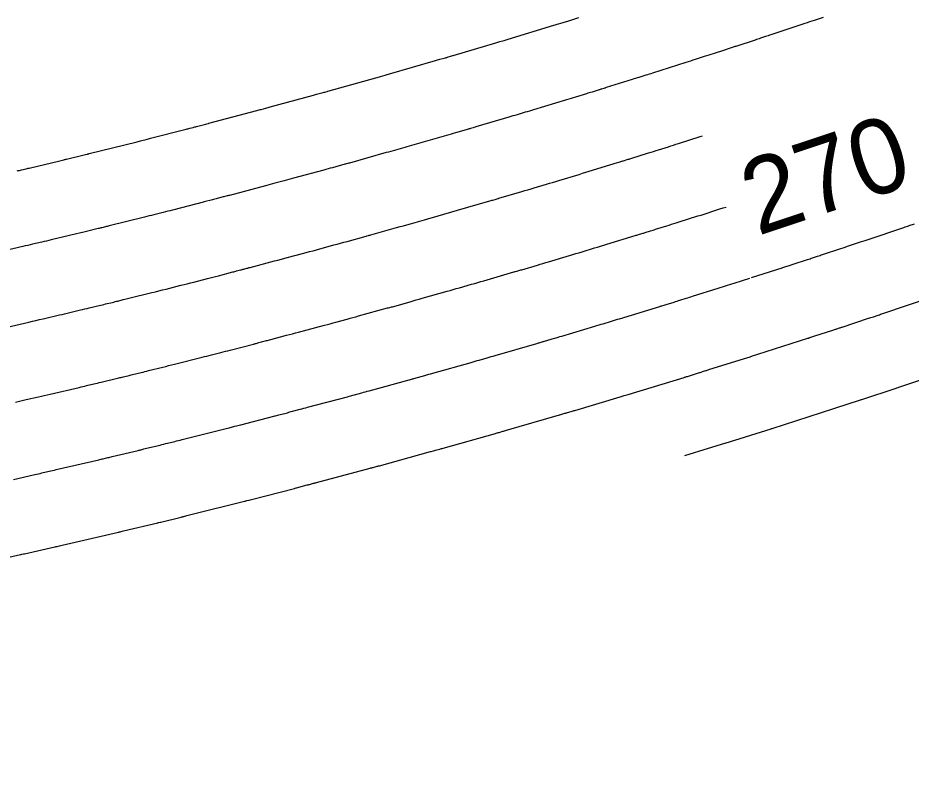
# Model space of a CAD drawing. Extents: x 1710723 to 1713003, y 548603 to 551142.
# Drawn here: x 1711864.8 to 1711936.3, y 549143.7 to 549204.1 of the extents above; entities that cross this region are included whole.
import ezdxf

# ---------------------------------------------------------------- set-up
doc = ezdxf.new("R2010")
doc.units = 0
for name, color, linetype in [('R_Contour Annot', 7, 'Continuous'), ('R_Contours', 7, 'Continuous'), ('R_Horz Alg', 7, 'Continuous')]:
    doc.layers.add(name, color=color, linetype=linetype)

msp = doc.modelspace()

# ---------------------------------------------------------------- linework, layer by layer
at = {"layer": 'R_Contours'}
for points in [[(1711929.262, 549204.147), (1711928.537, 549203.903), (1711928.356, 549203.842), (1711928.175, 549203.781), (1711927.994, 549203.721), (1711927.813, 549203.66), (1711925.076, 549202.746), (1711924.972, 549202.711), (1711924.869, 549202.677), (1711924.765, 549202.642), (1711924.661, 549202.608), (1711924.246, 549202.471), (1711924.142, 549202.437), (1711924.038, 549202.402), (1711923.934, 549202.368), (1711923.83, 549202.334), (1711922.285, 549201.828), (1711922.209, 549201.803), (1711922.132, 549201.777), (1711922.055, 549201.752), (1711921.978, 549201.727), (1711921.671, 549201.627), (1711921.594, 549201.602), (1711921.517, 549201.577), (1711921.44, 549201.552), (1711921.363, 549201.527), (1711920.457, 549201.233), (1711920.28, 549201.176), (1711920.104, 549201.119), (1711919.927, 549201.062), (1711919.75, 549201.005), (1711919.012, 549200.769), (1711918.83, 549200.71), (1711918.649, 549200.652), (1711918.467, 549200.594), (1711918.285, 549200.536), (1711915.597, 549199.68), (1711915.463, 549199.637), (1711915.329, 549199.595), (1711915.195, 549199.553), (1711915.061, 549199.511), (1711914.525, 549199.342), (1711914.391, 549199.3), (1711914.257, 549199.258), (1711914.123, 549199.216), (1711913.989, 549199.175), (1711911.901, 549198.523), (1711911.853, 549198.508), (1711911.805, 549198.494), (1711911.758, 549198.479), (1711911.71, 549198.464), (1711911.519, 549198.405), (1711911.471, 549198.39), (1711911.423, 549198.375), (1711911.376, 549198.36), (1711911.328, 549198.346), (1711910.765, 549198.172), (1711910.655, 549198.139), (1711910.546, 549198.105), (1711910.436, 549198.071), (1711910.326, 549198.038), (1711909.449, 549197.77), (1711909.266, 549197.714), (1711909.084, 549197.659), (1711908.901, 549197.603), (1711908.718, 549197.548), (1711906.082, 549196.748), (1711905.917, 549196.699), (1711905.753, 549196.649), (1711905.588, 549196.6), (1711905.424, 549196.551), (1711904.765, 549196.355), (1711904.601, 549196.306), (1711904.436, 549196.257), (1711904.272, 549196.208), (1711904.107, 549196.159), (1711901.473, 549195.379), (1711901.418, 549195.363), (1711901.307, 549195.331), (1711901.252, 549195.314), (1711901.036, 549195.251), (1711900.993, 549195.239), (1711900.951, 549195.227), (1711900.909, 549195.214), (1711900.867, 549195.202), (1711899.849, 549194.907), (1711899.665, 549194.854), (1711899.482, 549194.801), (1711899.298, 549194.748), (1711899.114, 549194.695), (1711896.509, 549193.944), (1711896.325, 549193.892), (1711896.141, 549193.839), (1711895.956, 549193.787), (1711895.772, 549193.735), (1711895.035, 549193.527), (1711894.851, 549193.475), (1711894.667, 549193.423), (1711894.483, 549193.371), (1711894.298, 549193.32), (1711891.344, 549192.491), (1711891.299, 549192.478), (1711891.209, 549192.453), (1711891.077, 549192.417), (1711891.026, 549192.403), (1711890.974, 549192.388), (1711889.985, 549192.117), (1711889.812, 549192.07), (1711889.638, 549192.022), (1711889.465, 549191.975), (1711889.292, 549191.928), (1711886.864, 549191.266), (1711886.679, 549191.215), (1711886.494, 549191.165), (1711886.309, 549191.115), (1711886.123, 549191.066), (1711885.382, 549190.868), (1711885.196, 549190.819), (1711885.011, 549190.769), (1711884.826, 549190.72), (1711884.64, 549190.671), (1711881.741, 549189.901), (1711881.7, 549189.89), (1711881.658, 549189.879), (1711881.617, 549189.868), (1711881.576, 549189.857), (1711881.369, 549189.803), (1711881.286, 549189.781), (1711881.245, 549189.771), (1711880.764, 549189.645), (1711880.67, 549189.621), (1711880.576, 549189.596), (1711880.482, 549189.572), (1711880.388, 549189.548), (1711879.71, 549189.373), (1711879.566, 549189.335), (1711879.422, 549189.298), (1711879.277, 549189.261), (1711879.133, 549189.224), (1711877.187, 549188.723), (1711877.001, 549188.676), (1711876.814, 549188.628), (1711876.628, 549188.581), (1711876.441, 549188.534), (1711875.694, 549188.347), (1711875.508, 549188.3), (1711875.321, 549188.254), (1711875.134, 549188.207), (1711874.948, 549188.16), (1711872.105, 549187.452), (1711872.033, 549187.434), (1711871.961, 549187.416), (1711871.889, 549187.398), (1711871.817, 549187.381), (1711871.529, 549187.31), (1711871.457, 549187.293), (1711871.385, 549187.275), (1711871.313, 549187.258), (1711871.241, 549187.24), (1711870.315, 549187.015), (1711870.2, 549186.987), (1711870.086, 549186.96), (1711869.971, 549186.932), (1711869.856, 549186.905), (1711869.397, 549186.795), (1711869.282, 549186.767), (1711869.167, 549186.74), (1711869.052, 549186.712), (1711868.937, 549186.685), (1711867.473, 549186.336), (1711867.285, 549186.291), (1711867.098, 549186.247), (1711866.91, 549186.203), (1711866.722, 549186.159), (1711865.971, 549185.985), (1711865.783, 549185.941), (1711865.595, 549185.898), (1711865.407, 549185.855), (1711865.219, 549185.811), (1711862.431, 549185.167)], [(1711864.754, 549191.862), (1711864.842, 549191.882), (1711864.931, 549191.903), (1711865.019, 549191.923), (1711865.108, 549191.944), (1711865.462, 549192.026), (1711865.551, 549192.047), (1711865.639, 549192.067), (1711865.728, 549192.088), (1711865.816, 549192.109), (1711868.052, 549192.642), (1711868.161, 549192.668), (1711868.27, 549192.694), (1711868.487, 549192.746), (1711868.542, 549192.759), (1711868.596, 549192.772), (1711868.651, 549192.786), (1711868.705, 549192.799), (1711870.11, 549193.14), (1711870.213, 549193.165), (1711870.384, 549193.207), (1711870.418, 549193.215), (1711870.452, 549193.224), (1711870.486, 549193.232), (1711870.52, 549193.241), (1711874.363, 549194.199), (1711874.452, 549194.221), (1711874.541, 549194.243), (1711874.631, 549194.266), (1711874.72, 549194.288), (1711875.077, 549194.377), (1711875.166, 549194.4), (1711875.255, 549194.422), (1711875.344, 549194.445), (1711875.433, 549194.468), (1711878.284, 549195.201), (1711878.354, 549195.219), (1711878.423, 549195.237), (1711878.492, 549195.255), (1711878.562, 549195.273), (1711878.839, 549195.344), (1711878.908, 549195.362), (1711878.978, 549195.38), (1711879.047, 549195.398), (1711879.116, 549195.416), (1711879.85, 549195.608), (1711879.93, 549195.628), (1711880.029, 549195.654), (1711880.069, 549195.665), (1711880.089, 549195.67), (1711883.936, 549196.692), (1711884.026, 549196.716), (1711884.116, 549196.74), (1711884.206, 549196.763), (1711884.295, 549196.787), (1711884.655, 549196.883), (1711884.745, 549196.907), (1711884.835, 549196.931), (1711884.924, 549196.956), (1711885.014, 549196.98), (1711888.472, 549197.924), (1711888.557, 549197.947), (1711888.642, 549197.97), (1711888.726, 549197.993), (1711888.811, 549198.016), (1711889.257, 549198.138), (1711889.319, 549198.155), (1711889.382, 549198.173), (1711889.574, 549198.226), (1711889.623, 549198.24), (1711893.473, 549199.32), (1711893.564, 549199.345), (1711893.655, 549199.371), (1711893.746, 549199.396), (1711893.837, 549199.422), (1711894.2, 549199.524), (1711894.291, 549199.55), (1711894.381, 549199.576), (1711894.472, 549199.602), (1711894.563, 549199.628), (1711898.229, 549200.684), (1711898.32, 549200.71), (1711898.411, 549200.736), (1711898.503, 549200.763), (1711898.594, 549200.789), (1711899.04, 549200.918), (1711899.091, 549200.933), (1711899.142, 549200.948), (1711899.193, 549200.963), (1711899.244, 549200.978), (1711899.54, 549201.064), (1711899.622, 549201.088), (1711899.64, 549201.094), (1711903.068, 549202.108), (1711903.151, 549202.133), (1711903.233, 549202.157), (1711903.316, 549202.182), (1711903.398, 549202.206), (1711903.729, 549202.305), (1711903.812, 549202.33), (1711903.894, 549202.354), (1711903.977, 549202.379), (1711904.059, 549202.404), (1711907.711, 549203.511), (1711907.804, 549203.54), (1711907.896, 549203.568), (1711907.989, 549203.596), (1711908.082, 549203.624), (1711908.452, 549203.737), (1711908.545, 549203.766), (1711908.638, 549203.794), (1711908.73, 549203.822), (1711908.823, 549203.851), (1711909.642, 549204.103), (1711909.714, 549204.126)], [(1711863.948, 549179.359), (1711865.685, 549179.76), (1711865.972, 549179.827), (1711866.26, 549179.893), (1711866.547, 549179.96), (1711866.834, 549180.026), (1711868.151, 549180.332), (1711868.354, 549180.379), (1711868.556, 549180.426), (1711868.758, 549180.474), (1711868.96, 549180.522), (1711869.822, 549180.728), (1711869.997, 549180.769), (1711870.173, 549180.811), (1711870.348, 549180.853), (1711870.523, 549180.895), (1711871.321, 549181.086), (1711871.448, 549181.116), (1711871.575, 549181.147), (1711871.702, 549181.178), (1711871.829, 549181.209), (1711872.372, 549181.34), (1711872.482, 549181.367), (1711872.592, 549181.394), (1711872.701, 549181.421), (1711872.811, 549181.447), (1711873.25, 549181.554), (1711873.36, 549181.581), (1711873.47, 549181.608), (1711873.579, 549181.635), (1711873.689, 549181.663), (1711875.532, 549182.122), (1711875.816, 549182.193), (1711876.101, 549182.264), (1711876.385, 549182.335), (1711876.669, 549182.406), (1711877.861, 549182.705), (1711878.117, 549182.769), (1711878.373, 549182.834), (1711878.629, 549182.899), (1711878.885, 549182.965), (1711879.981, 549183.246), (1711880.201, 549183.303), (1711880.42, 549183.359), (1711880.639, 549183.416), (1711880.859, 549183.473), (1711882.026, 549183.774), (1711882.1, 549183.793), (1711882.174, 549183.812), (1711882.248, 549183.832), (1711882.322, 549183.851), (1711882.64, 549183.934), (1711882.702, 549183.95), (1711882.765, 549183.966), (1711882.828, 549183.983), (1711882.891, 549183.999), (1711883.142, 549184.065), (1711883.205, 549184.082), (1711883.268, 549184.098), (1711883.331, 549184.115), (1711883.393, 549184.131), (1711885.344, 549184.65), (1711885.625, 549184.724), (1711885.906, 549184.799), (1711886.187, 549184.874), (1711886.468, 549184.949), (1711887.592, 549185.248), (1711887.873, 549185.323), (1711888.154, 549185.399), (1711888.434, 549185.475), (1711888.715, 549185.551), (1711890.111, 549185.932), (1711890.373, 549186.004), (1711890.635, 549186.075), (1711890.897, 549186.147), (1711891.159, 549186.219), (1711892.691, 549186.639), (1711892.753, 549186.655), (1711892.878, 549186.69), (1711892.929, 549186.704), (1711893.014, 549186.728), (1711893.065, 549186.742), (1711895.123, 549187.319), (1711895.401, 549187.397), (1711895.679, 549187.475), (1711895.956, 549187.554), (1711896.234, 549187.632), (1711897.345, 549187.945), (1711897.622, 549188.024), (1711897.9, 549188.102), (1711898.177, 549188.182), (1711898.455, 549188.261), (1711900, 549188.706), (1711900.276, 549188.786), (1711900.552, 549188.866), (1711900.828, 549188.946), (1711901.104, 549189.025), (1711902.693, 549189.486), (1711902.76, 549189.505), (1711902.827, 549189.525), (1711903.002, 549189.576), (1711903.084, 549189.6), (1711903.223, 549189.641), (1711903.278, 549189.657), (1711903.305, 549189.665), (1711905.146, 549190.21), (1711905.392, 549190.283), (1711905.639, 549190.356), (1711905.886, 549190.429), (1711906.132, 549190.503), (1711907.118, 549190.796), (1711907.365, 549190.87), (1711907.611, 549190.944), (1711907.858, 549191.018), (1711908.104, 549191.092), (1711909.725, 549191.584), (1711909.998, 549191.667), (1711910.271, 549191.75), (1711910.544, 549191.833), (1711910.817, 549191.916), (1711912.278, 549192.362), (1711912.366, 549192.389), (1711912.454, 549192.416), (1711912.542, 549192.443), (1711912.629, 549192.47), (1711913.014, 549192.588), (1711913.085, 549192.61), (1711913.157, 549192.632), (1711913.228, 549192.654), (1711913.299, 549192.676), (1711913.584, 549192.765), (1711913.655, 549192.787), (1711913.726, 549192.809), (1711913.798, 549192.831), (1711913.869, 549192.853), (1711915.293, 549193.297), (1711915.492, 549193.36), (1711915.692, 549193.422), (1711915.891, 549193.484), (1711916.09, 549193.547), (1711916.888, 549193.797), (1711917.087, 549193.86), (1711917.287, 549193.923), (1711917.486, 549193.986), (1711917.685, 549194.049), (1711919.414, 549194.6), (1711919.598, 549194.659)], [(1711864.616, 549173.358), (1711864.828, 549173.406), (1711865.041, 549173.454), (1711865.253, 549173.502), (1711865.465, 549173.551), (1711866.453, 549173.779), (1711866.689, 549173.834), (1711866.924, 549173.888), (1711867.159, 549173.943), (1711867.395, 549173.997), (1711869.723, 549174.537), (1711869.869, 549174.571), (1711870.015, 549174.606), (1711870.16, 549174.64), (1711870.306, 549174.674), (1711870.888, 549174.813), (1711871.033, 549174.848), (1711871.178, 549174.883), (1711871.324, 549174.917), (1711871.469, 549174.952), (1711872.881, 549175.29), (1711872.973, 549175.312), (1711873.064, 549175.334), (1711873.156, 549175.356), (1711873.248, 549175.379), (1711873.615, 549175.468), (1711873.706, 549175.49), (1711873.798, 549175.512), (1711873.89, 549175.535), (1711873.982, 549175.557), (1711874.684, 549175.728), (1711874.831, 549175.764), (1711874.979, 549175.801), (1711875.126, 549175.837), (1711875.273, 549175.874), (1711876.405, 549176.156), (1711876.642, 549176.215), (1711876.88, 549176.274), (1711877.118, 549176.334), (1711877.355, 549176.393), (1711879.561, 549176.945), (1711879.747, 549176.992), (1711879.933, 549177.039), (1711880.118, 549177.086), (1711880.304, 549177.134), (1711881.047, 549177.325), (1711881.233, 549177.373), (1711881.418, 549177.421), (1711881.604, 549177.469), (1711881.79, 549177.516), (1711883.665, 549178.001), (1711883.719, 549178.014), (1711883.772, 549178.028), (1711883.826, 549178.042), (1711883.88, 549178.056), (1711884.095, 549178.113), (1711884.203, 549178.141), (1711884.311, 549178.169), (1711884.709, 549178.273), (1711884.793, 549178.295), (1711884.877, 549178.318), (1711884.961, 549178.34), (1711885.046, 549178.362), (1711886.321, 549178.701), (1711886.561, 549178.765), (1711886.802, 549178.829), (1711887.042, 549178.893), (1711887.283, 549178.957), (1711889.358, 549179.51), (1711889.586, 549179.571), (1711889.813, 549179.632), (1711890.041, 549179.694), (1711890.268, 549179.756), (1711891.177, 549180.004), (1711891.405, 549180.066), (1711891.632, 549180.128), (1711891.859, 549180.19), (1711892.086, 549180.252), (1711894.409, 549180.889), (1711894.469, 549180.905), (1711894.574, 549180.934), (1711894.718, 549180.974), (1711894.763, 549180.987), (1711894.786, 549180.993), (1711896.203, 549181.391), (1711896.447, 549181.459), (1711896.691, 549181.528), (1711896.934, 549181.596), (1711897.178, 549181.665), (1711899.168, 549182.226), (1711899.414, 549182.296), (1711899.659, 549182.365), (1711899.905, 549182.436), (1711900.15, 549182.506), (1711901.131, 549182.789), (1711901.377, 549182.859), (1711901.622, 549182.93), (1711901.867, 549183.001), (1711902.113, 549183.072), (1711904.519, 549183.769), (1711904.569, 549183.784), (1711904.619, 549183.798), (1711904.744, 549183.835), (1711904.819, 549183.857), (1711904.991, 549183.907), (1711905.064, 549183.929), (1711905.138, 549183.951), (1711906.398, 549184.324), (1711906.62, 549184.389), (1711906.842, 549184.455), (1711907.064, 549184.521), (1711907.286, 549184.587), (1711908.972, 549185.089), (1711909.221, 549185.164), (1711909.47, 549185.238), (1711909.719, 549185.313), (1711909.967, 549185.388), (1711910.961, 549185.69), (1711911.21, 549185.765), (1711911.458, 549185.841), (1711911.707, 549185.916), (1711911.955, 549185.992), (1711914.23, 549186.686), (1711914.296, 549186.706), (1711914.362, 549186.726), (1711914.428, 549186.747), (1711914.494, 549186.767), (1711914.758, 549186.848), (1711914.824, 549186.869), (1711914.89, 549186.889), (1711914.956, 549186.91), (1711915.022, 549186.93), (1711915.458, 549187.065), (1711915.553, 549187.095), (1711915.647, 549187.124), (1711915.742, 549187.153), (1711915.837, 549187.183), (1711916.757, 549187.47), (1711916.941, 549187.528), (1711917.126, 549187.585), (1711917.311, 549187.643), (1711917.496, 549187.701), (1711918.74, 549188.092), (1711918.992, 549188.171), (1711919.244, 549188.251), (1711919.496, 549188.33), (1711919.747, 549188.41), (1711920.754, 549188.731), (1711921.006, 549188.811), (1711921.258, 549188.892), (1711921.494, 549188.967)], [(1711923.539, 549183.324), (1711925.976, 549184.106), (1711926.049, 549184.13), (1711926.123, 549184.153), (1711926.197, 549184.177), (1711926.271, 549184.201), (1711926.566, 549184.297), (1711926.64, 549184.321), (1711926.713, 549184.345), (1711926.787, 549184.369), (1711926.861, 549184.393), (1711928.013, 549184.769), (1711928.114, 549184.801), (1711928.214, 549184.834), (1711928.314, 549184.867), (1711928.414, 549184.9), (1711928.816, 549185.031), (1711928.916, 549185.064), (1711929.016, 549185.097), (1711929.116, 549185.13), (1711929.217, 549185.163), (1711930.683, 549185.648), (1711930.859, 549185.706), (1711931.035, 549185.764), (1711931.211, 549185.823), (1711931.387, 549185.881), (1711932.09, 549186.116), (1711932.265, 549186.175), (1711932.441, 549186.234), (1711932.617, 549186.293), (1711932.793, 549186.352), (1711935.727, 549187.339), (1711935.832, 549187.375), (1711935.937, 549187.41), (1711936.042, 549187.446), (1711936.147, 549187.482), (1711936.568, 549187.625)], [(1711864.466, 549167.174), (1711866.164, 549167.556), (1711866.306, 549167.588), (1711866.449, 549167.621), (1711866.591, 549167.653), (1711866.734, 549167.686), (1711867.304, 549167.818), (1711867.446, 549167.85), (1711867.588, 549167.883), (1711867.731, 549167.916), (1711867.873, 549167.949), (1711871.295, 549168.743), (1711871.384, 549168.764), (1711871.473, 549168.785), (1711871.562, 549168.806), (1711871.651, 549168.827), (1711872.006, 549168.912), (1711872.095, 549168.933), (1711872.184, 549168.954), (1711872.273, 549168.975), (1711872.362, 549168.997), (1711874.441, 549169.494), (1711874.498, 549169.508), (1711874.554, 549169.521), (1711874.61, 549169.535), (1711874.667, 549169.548), (1711874.892, 549169.603), (1711875.005, 549169.631), (1711875.117, 549169.658), (1711876.194, 549169.921), (1711876.341, 549169.957), (1711876.487, 549169.993), (1711876.634, 549170.029), (1711876.781, 549170.065), (1711877.367, 549170.212), (1711877.513, 549170.248), (1711877.66, 549170.285), (1711877.806, 549170.321), (1711877.953, 549170.358), (1711881.26, 549171.186), (1711881.376, 549171.215), (1711881.492, 549171.244), (1711881.608, 549171.274), (1711881.723, 549171.303), (1711882.186, 549171.422), (1711882.301, 549171.452), (1711882.417, 549171.482), (1711882.532, 549171.512), (1711882.648, 549171.542), (1711885.303, 549172.227), (1711885.371, 549172.245), (1711885.438, 549172.262), (1711885.607, 549172.306), (1711885.708, 549172.333), (1711886.275, 549172.481), (1711886.381, 549172.509), (1711886.487, 549172.537), (1711886.592, 549172.565), (1711886.698, 549172.593), (1711887.394, 549172.778), (1711887.546, 549172.818), (1711887.697, 549172.858), (1711887.848, 549172.898), (1711888, 549172.939), (1711891.183, 549173.788), (1711891.328, 549173.827), (1711891.473, 549173.865), (1711891.617, 549173.905), (1711891.762, 549173.944), (1711892.34, 549174.101), (1711892.484, 549174.141), (1711892.629, 549174.18), (1711892.773, 549174.22), (1711892.917, 549174.259), (1711896.126, 549175.139), (1711896.164, 549175.149), (1711896.241, 549175.171), (1711896.393, 549175.213), (1711896.45, 549175.229), (1711896.507, 549175.245), (1711897.389, 549175.492), (1711897.546, 549175.536), (1711897.702, 549175.58), (1711897.859, 549175.624), (1711898.015, 549175.668), (1711901.1, 549176.538), (1711901.259, 549176.583), (1711901.419, 549176.628), (1711901.578, 549176.674), (1711901.737, 549176.72), (1711902.374, 549176.903), (1711902.533, 549176.949), (1711902.692, 549176.995), (1711902.852, 549177.041), (1711903.011, 549177.087), (1711906.346, 549178.053), (1711906.395, 549178.067), (1711906.493, 549178.096), (1711906.542, 549178.11), (1711906.786, 549178.182), (1711906.832, 549178.195), (1711906.878, 549178.209), (1711906.924, 549178.223), (1711906.97, 549178.236), (1711907.753, 549178.468), (1711907.899, 549178.511), (1711908.045, 549178.555), (1711908.191, 549178.598), (1711908.337, 549178.641), (1711910.999, 549179.434), (1711911.164, 549179.483), (1711911.329, 549179.533), (1711911.493, 549179.582), (1711911.658, 549179.632), (1711912.317, 549179.832), (1711912.481, 549179.882), (1711912.646, 549179.932), (1711912.81, 549179.982), (1711912.975, 549180.032), (1711916.181, 549181.01), (1711916.226, 549181.024), (1711916.27, 549181.037), (1711916.314, 549181.051), (1711916.358, 549181.064), (1711916.535, 549181.119), (1711916.623, 549181.146), (1711916.712, 549181.174), (1711917.332, 549181.366), (1711917.45, 549181.403), (1711917.568, 549181.439), (1711917.687, 549181.476), (1711917.805, 549181.513), (1711918.313, 549181.671), (1711918.437, 549181.71), (1711918.561, 549181.749), (1711918.685, 549181.788), (1711918.809, 549181.826), (1711920.861, 549182.471), (1711921.031, 549182.524), (1711921.201, 549182.578), (1711921.372, 549182.632), (1711921.542, 549182.686), (1711922.222, 549182.903), (1711922.392, 549182.957), (1711922.563, 549183.011), (1711922.733, 549183.066), (1711922.903, 549183.12), (1711923.39, 549183.277)], [(1711862.984, 549160.701), (1711865.019, 549161.149), (1711865.071, 549161.161), (1711865.124, 549161.173), (1711865.255, 549161.202), (1711865.334, 549161.22), (1711867.757, 549161.765), (1711867.807, 549161.776), (1711867.857, 549161.787), (1711867.906, 549161.798), (1711867.956, 549161.81), (1711868.154, 549161.856), (1711868.253, 549161.879), (1711868.352, 549161.902), (1711872.867, 549162.949), (1711872.899, 549162.956), (1711872.931, 549162.964), (1711872.964, 549162.971), (1711872.996, 549162.979), (1711873.158, 549163.018), (1711873.255, 549163.041), (1711876.001, 549163.698), (1711876.043, 549163.708), (1711876.085, 549163.718), (1711876.211, 549163.749), (1711876.253, 549163.759), (1711877.886, 549164.158), (1711877.941, 549164.171), (1711877.996, 549164.185), (1711878.052, 549164.198), (1711878.107, 549164.212), (1711878.329, 549164.267), (1711878.439, 549164.295), (1711878.55, 549164.323), (1711882.96, 549165.427), (1711883.006, 549165.438), (1711883.051, 549165.45), (1711883.097, 549165.461), (1711883.142, 549165.473), (1711883.324, 549165.52), (1711883.415, 549165.543), (1711883.506, 549165.567), (1711886.941, 549166.454), (1711886.996, 549166.468), (1711887.092, 549166.493), (1711887.106, 549166.497), (1711887.972, 549166.723), (1711888.034, 549166.74), (1711888.096, 549166.756), (1711888.158, 549166.772), (1711888.22, 549166.789), (1711888.468, 549166.855), (1711888.53, 549166.871), (1711888.592, 549166.888), (1711888.654, 549166.904), (1711888.717, 549166.921), (1711893.009, 549168.066), (1711893.071, 549168.082), (1711893.132, 549168.099), (1711893.194, 549168.115), (1711893.256, 549168.132), (1711893.502, 549168.199), (1711893.564, 549168.216), (1711893.625, 549168.233), (1711893.687, 549168.25), (1711893.749, 549168.267), (1711897.843, 549169.389), (1711897.894, 549169.403), (1711898.091, 549169.458), (1711898.16, 549169.477), (1711898.228, 549169.496), (1711898.576, 549169.593), (1711898.645, 549169.613), (1711898.714, 549169.632), (1711898.784, 549169.652), (1711898.853, 549169.671), (1711903.032, 549170.85), (1711903.105, 549170.87), (1711903.178, 549170.891), (1711903.251, 549170.912), (1711903.324, 549170.933), (1711903.617, 549171.017), (1711903.69, 549171.038), (1711903.763, 549171.059), (1711903.836, 549171.081), (1711903.909, 549171.102), (1711908.172, 549172.336), (1711908.203, 549172.345), (1711908.265, 549172.364), (1711908.582, 549172.457), (1711908.637, 549172.473), (1711908.692, 549172.489), (1711908.748, 549172.506), (1711908.803, 549172.522), (1711909.109, 549172.613), (1711909.179, 549172.633), (1711909.248, 549172.654), (1711909.317, 549172.674), (1711909.387, 549172.695), (1711913.026, 549173.778), (1711913.107, 549173.803), (1711913.187, 549173.827), (1711913.268, 549173.851), (1711913.349, 549173.876), (1711913.672, 549173.973), (1711913.752, 549173.998), (1711913.833, 549174.023), (1711913.914, 549174.047), (1711913.994, 549174.072), (1711918.133, 549175.334), (1711918.178, 549175.348), (1711918.223, 549175.362), (1711918.334, 549175.396), (1711918.401, 549175.417), (1711919.363, 549175.715), (1711919.426, 549175.735), (1711919.49, 549175.754), (1711919.553, 549175.774), (1711919.616, 549175.794), (1711919.869, 549175.873), (1711919.932, 549175.892), (1711919.995, 549175.912), (1711920.058, 549175.932), (1711920.122, 549175.952), (1711922.981, 549176.85), (1711923.07, 549176.877), (1711923.159, 549176.905), (1711923.247, 549176.933), (1711923.336, 549176.962), (1711923.69, 549177.075), (1711923.779, 549177.103), (1711923.867, 549177.131), (1711923.956, 549177.159), (1711924.044, 549177.188), (1711928.051, 549178.473), (1711928.09, 549178.485), (1711928.13, 549178.498), (1711928.169, 549178.511), (1711928.209, 549178.524), (1711928.367, 549178.575), (1711928.446, 549178.6), (1711928.524, 549178.626), (1711930.133, 549179.151), (1711930.187, 549179.169), (1711930.241, 549179.186), (1711930.296, 549179.204), (1711930.35, 549179.222), (1711930.567, 549179.293), (1711930.621, 549179.311), (1711930.676, 549179.329), (1711930.73, 549179.347), (1711930.784, 549179.365), (1711932.897, 549180.063), (1711932.994, 549180.095), (1711933.091, 549180.127), (1711933.187, 549180.159), (1711933.284, 549180.191), (1711933.67, 549180.32), (1711933.767, 549180.352), (1711933.863, 549180.385), (1711933.96, 549180.417), (1711934.056, 549180.449), (1711937.923, 549181.751)], [(1711918.202, 549169.084), (1711920.085, 549169.659), (1711920.091, 549169.66), (1711921.408, 549170.069), (1711921.434, 549170.077), (1711925.102, 549171.228), (1711925.13, 549171.237), (1711925.186, 549171.255), (1711930.126, 549172.84), (1711930.188, 549172.86), (1711932.252, 549173.533), (1711932.335, 549173.56), (1711932.352, 549173.566), (1711935.111, 549174.477), (1711935.164, 549174.495), (1711935.268, 549174.53), (1711935.32, 549174.547), (1711940.119, 549176.162)]]:
    msp.add_lwpolyline(points, dxfattribs=at)
at = {"layer": 'R_Horz Alg'}
msp.add_arc((1711777.174, 549719.88), 636.62, 271.078651, 340.773399, dxfattribs=at)

# ---------------------------------------------------------------- texts
at = {"layer": 'R_Contour Annot'}
msp.add_text('270', height=6, rotation=18.42422, dxfattribs=at).set_placement((1711924.011, 549186.644))

doc.saveas('drawing.dxf')
